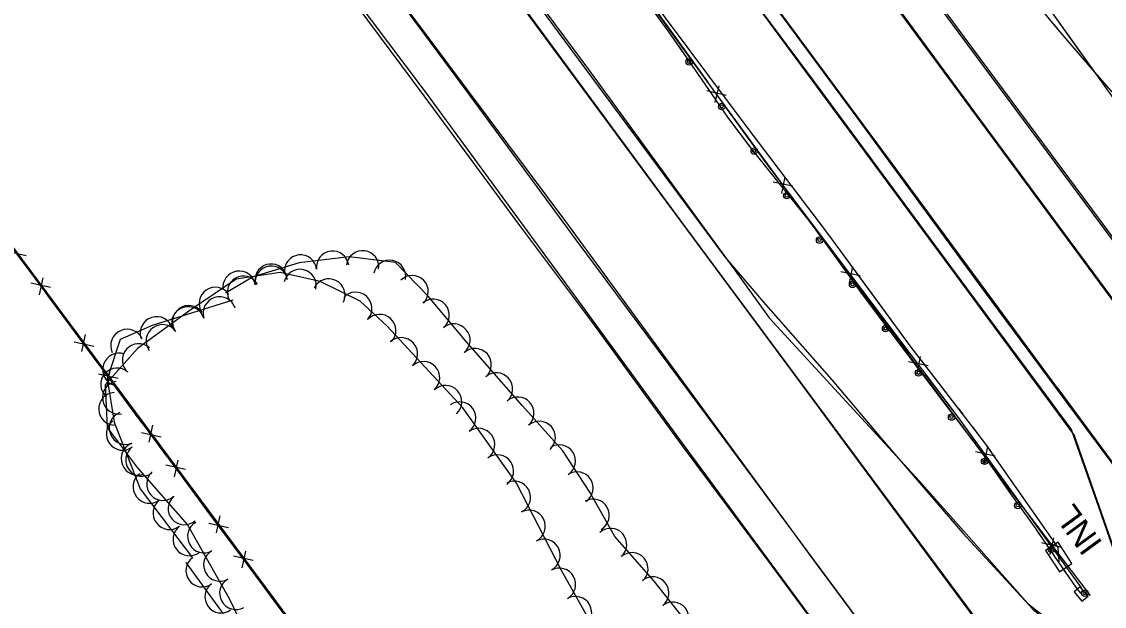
# Model space of a CAD drawing. Extents: x 353423 to 364002, y 127000 to 201942.
# Drawn here: x 360516.5 to 360782.5, y 130570.2 to 130713.8 of the extents above; entities that cross this region are included whole.
import ezdxf

# ---------------------------------------------------------------- set-up
doc = ezdxf.new("R2010")
doc.units = 0
for name, color, linetype in [('E_DTM_SlopeBottom', 7, 'Continuous'), ('E_DTM_SlopeTop', 7, 'Continuous'), ('E_FEN_Generic', 7, 'Continuous'), ('E_MISCPROP', 7, 'Continuous'), ('E_STRUCT_WingWall', 7, 'Continuous')]:
    doc.layers.add(name, color=color, linetype=linetype)

msp = doc.modelspace()

# ---------------------------------------------------------------- linework, layer by layer
at = {"layer": 'E_DTM_SlopeBottom'}
for p, q in [((360686.93, 130693.93), (360687.86, 130698.02)), ((360689.63, 130695.68), (360684.87, 130696.79)), ((360705.93, 130673.4), (360701.14, 130674.4)), ((360703.26, 130671.59), (360704.1, 130675.7)), ((360512.84, 130657.43), (360517.64, 130656.38)), ((360722.57, 130651.33), (360717.79, 130652.34)), ((360719.91, 130649.53), (360720.75, 130653.64)), ((360520.89, 130646.74), (360521.78, 130650.87)), ((360523.6, 130648.53), (360518.78, 130649.59)), ((360532.09, 130636.93), (360531.21, 130632.81)), ((360529.4, 130635.14), (360534.2, 130634.09)), ((360736.55, 130627.46), (360737.39, 130631.57)), ((360537.47, 130624.35), (360538.36, 130628.48)), ((360739.22, 130629.26), (360734.43, 130630.27)), ((360540.18, 130626.14), (360535.36, 130627.2)), ((360545.95, 130612.86), (360550.75, 130611.81)), ((360548.64, 130614.65), (360547.77, 130610.53)), ((360755.68, 130607.02), (360750.92, 130608.12)), ((360752.98, 130605.27), (360753.9, 130609.36)), ((360556.78, 130603.77), (360551.96, 130604.82)), ((360554.08, 130601.97), (360554.95, 130606.11)), ((360565.2, 130592.36), (360564.33, 130588.24)), ((360562.51, 130590.57), (360567.31, 130589.52)), ((360769.2, 130582.88), (360770.12, 130586.98)), ((360570.7, 130579.62), (360571.58, 130583.75)), ((360771.9, 130584.63), (360767.13, 130585.73)), ((360573.4, 130581.41), (360568.59, 130582.46))]:
    msp.add_line(p, q, dxfattribs=at)
for points in [[(360776.97, 130574.69), (360746.67, 130616.52), (360699.41, 130679.17), (360658.68, 130735.65), (360605.88, 130806.93), (360546.91, 130886.24), (360510.01, 130936.13), (360465.18, 130997.46), (360404.07, 131080.41), (360366.6, 131130.68)], [(361092.35, 129877.19), (361044.92, 129941.89), (360997.56, 130006.24), (360962.5, 130053.48), (360925.13, 130103.47), (360878.83, 130166.15), (360830.3, 130231.49), (360791.79, 130283.41), (360741.39, 130351.57), (360693.7, 130416.36), (360638.93, 130490.09), (360591.48, 130554.19), (360546.89, 130614.15), (360499.36, 130678.34), (360464.05, 130726.01), (360438.2, 130761.06), (360411.43, 130797.18), (360381.21, 130837.79)], [(360407.27, 130804.74), (360439.73, 130759.75), (360490.26, 130690.73), (360670.73, 130447.81), (360721.87, 130378.76), (360826.04, 130237.28), (360883.23, 130160.42), (360930.64, 130096.44), (361000.73, 130001.84), (361082.18, 129891.3), (361106.51, 129856.97), (361154.89, 129791.52), (361182.92, 129753.46), (361188.88, 129640.57), (361196.9, 129546.21), (361209.22, 129452.29), (361221.13, 129367.62), (361233.6, 129282.65)], [(360678.52, 130708.14), (360672.74, 130716.15)], [(360685.09, 130699.03), (360678.52, 130708.14)], [(360694.68, 130685.72), (360688.91, 130693.73)], [(360701.31, 130676.65), (360699.41, 130679.17), (360694.68, 130685.72)], [(360711.19, 130663.55), (360705.24, 130671.44)], [(360717.96, 130654.58), (360711.19, 130663.55)], [(360518.97, 130651.85), (360512.23, 130660.95)], [(360517.45, 130654.12), (360524.18, 130645.07)], [(360727.84, 130641.48), (360721.89, 130649.37)], [(360528.82, 130638.56), (360522.89, 130646.56)], [(360524.18, 130645.07), (360530.1, 130637.1)], [(360734.6, 130632.51), (360727.84, 130641.48)], [(360535.55, 130629.46), (360528.82, 130638.56)], [(360534.01, 130631.84), (360540.74, 130622.78)], [(360744.48, 130619.42), (360738.53, 130627.3)], [(360545.4, 130616.17), (360539.47, 130624.17)], [(360540.74, 130622.78), (360546.65, 130614.82)], [(360751.13, 130610.36), (360746.67, 130616.52), (360744.48, 130619.42)], [(360552.15, 130607.08), (360546.89, 130614.15), (360545.4, 130616.17)], [(360550.57, 130609.55), (360557.29, 130600.5)], [(360760.76, 130597.07), (360754.96, 130605.07)], [(360562.02, 130593.81), (360556.08, 130601.8)], [(360557.29, 130600.5), (360563.21, 130592.53)], [(360767.35, 130587.98), (360760.76, 130597.07)], [(360568.77, 130584.73), (360562.02, 130593.81)], [(360567.12, 130587.27), (360573.85, 130578.21)], [(360776.97, 130574.69), (360771.18, 130582.69)], [(360578.64, 130571.46), (360572.7, 130579.45)], [(360573.85, 130578.21), (360579.77, 130570.25)], [(360777.05, 130571.4), (360778.58, 130572.68), (360776.64, 130574.98), (360775.12, 130573.69), (360777.05, 130571.4)], [(360585.4, 130562.37), (360578.64, 130571.46)]]:
    msp.add_lwpolyline(points, dxfattribs=at)
msp.add_lwpolyline([(360774.59, 130580.69), (360771.16, 130585.9), (360768.1, 130583.88), (360771.53, 130578.67)], close=True, dxfattribs=at)
at = {"layer": 'E_DTM_SlopeTop'}
for points in [[(361333.55, 129917.72), (361268.46, 130006.01), (361189.85, 130112.75), (361142.67, 130176.31), (361088.86, 130249.79), (360994.04, 130376.87), (360928.62, 130465.05), (360871.56, 130543.5), (360815.21, 130618.95), (360766.71, 130684.28), (360721.66, 130745.05), (360677.21, 130805.9), (360595.4, 130915.9), (360546.5, 130984.06), (360499.99, 131045.42), (360426.96, 131144.04)], [(360419.47, 131139.59), (360478.07, 131059.84), (360541.82, 130973.68), (360588.71, 130910.37), (360647.11, 130831.47), (360699.04, 130761.76), (360750.66, 130691.62), (360805.87, 130616.86), (360864.14, 130537.84), (360910.27, 130475.6), (360951.2, 130420.07), (361004.77, 130348.23), (361046.61, 130292.04), (361097.13, 130223.94), (361149.43, 130153.39), (361185.11, 130104.98), (361238.11, 130033), (361245.88, 130022.49), (361278.08, 129978.64), (361333.1, 129905.4)], [(360337.83, 131131.57), (360358.59, 131103.63), (360410.73, 131033.01), (360469.38, 130953.56), (360514.36, 130893.15), (360555.3, 130837.54), (360604.51, 130771.17), (360655.75, 130702.06), (360692.79, 130651.26), (360700.18, 130641.04)], [(360392.82, 131129.19), (360439.78, 131065.72), (360491.21, 130996.27), (360566.57, 130894.7), (360647.89, 130784.33), (360688.43, 130729.6), (360741.87, 130657.22), (360775.19, 130612.07)], [(360770.85, 130623.99), (360731.32, 130677.71), (360684.37, 130741.2), (360627.35, 130818.29), (360564.03, 130903.58), (360518.64, 130964.96), (360463.16, 131040.47), (360396.39, 131130.9)], [(360812.38, 130484.47), (360679.44, 130663.54), (360601.08, 130770.21), (360543.32, 130848.21), (360486.67, 130924.56), (360443.57, 130982.64), (360405.94, 131033.09), (360347.68, 131112.32), (360339.61, 131123.22)], [(361334.82, 129736.64), (361276.43, 129817.07), (361218.41, 129895.06), (361173.92, 129955.59), (361116.6, 130033.88), (361057.88, 130112.91), (361005.23, 130183.79), (360919.7, 130299.92), (360859.57, 130381.04), (360802.73, 130458.17), (360712.34, 130579.92), (360650.2, 130664.74), (360583.26, 130754.37), (360522.68, 130834.6), (360443.16, 130936.49), (360381.32, 131015.53), (360355.42, 131048.77)], [(360359.06, 131031.63), (360412.77, 130962.23), (360456.51, 130906.46), (360514.58, 130829.11), (360575.61, 130749.78), (360615.66, 130696.58), (360651.09, 130648.19), (360678.79, 130610.26), (360711.14, 130566.37), (360768.38, 130488.8), (360811.24, 130431.97), (360853.39, 130374.54), (360875.99, 130343.44), (360911.98, 130295.27), (360943.46, 130251.36), (360971.6, 130213.46), (361000.8, 130174.05), (361030.19, 130135.22), (361061.21, 130091.97), (361110.81, 130026.56), (361166.93, 129950.76), (361239.61, 129851.93), (361335.43, 129723.6)], [(360915.39, 130428.25), (360885.77, 130468.28), (360854.3, 130510.8), (360823.95, 130551.75), (360794.76, 130591.46), (360773.92, 130619.47), (360751.38, 130649.91), (360722.07, 130689.97), (360692.78, 130729.59), (360658.7, 130775.33), (360626.52, 130818.94)], [(360539.14, 130812.53), (360565.51, 130777.84), (360593.87, 130739.91), (360625.54, 130697.03), (360652.65, 130660.22), (360685.53, 130616.09), (360714.56, 130576.84), (360749.27, 130530.18), (360775.57, 130494.65), (360810.61, 130447.18), (360838.14, 130409.72), (360879.43, 130354.21), (360906.49, 130317.48), (360944.28, 130266.52), (360972.83, 130227.69), (361006.65, 130182.14), (361037.04, 130141.05), (361070.51, 130095.92), (361098.26, 130058.32), (361129.55, 130016.03), (361157.08, 129978.62), (361188.2, 129936.52), (361215.22, 129899.89), (361236.43, 129871.54)], [(360787.07, 130577.55), (360781.17, 130594.57), (360775.15, 130611.63), (360774.45, 130613.59), (360767.1, 130623.57), (360748.79, 130648.37), (360729.58, 130674.29), (360711.81, 130698.39), (360689.89, 130727.84), (360668.06, 130757.8), (360647.03, 130785.8), (360625.85, 130814.41)], [(361335.19, 129902.03), (361317.97, 129925.09), (361294.2, 129957.22), (361266.66, 129994.48), (361242.03, 130027.81), (361217.11, 130061.23), (361186.78, 130102.37), (361155.57, 130144.32), (361126.8, 130183.16), (361098.06, 130221.84), (361070.02, 130259.76), (361036.43, 130304.8), (361006.19, 130345.98), (360970.52, 130394.27), (360936.12, 130440.54), (360901.22, 130487.47), (360871.26, 130528.04), (360838.83, 130571.83), (360808.58, 130612.92), (360780.05, 130651.51), (360745.78, 130697.86), (360715, 130739.66), (360684.42, 130781.1), (360659.61, 130814.18)], [(360529.26, 130810.15), (360554.27, 130777.79), (360574.26, 130750.78), (360595.98, 130721.64), (360615.36, 130695.63), (360638.79, 130663.72), (360656.49, 130640.14), (360678.56, 130609.95), (360700.65, 130580.24), (360724.42, 130548.06), (360743.96, 130521.7), (360768.43, 130488.72), (360792.03, 130456.94), (360810.78, 130431.34)], [(360570.32, 130810.78), (360600.22, 130770.91), (360638.59, 130718.65), (360671.71, 130673.89), (360707.05, 130626.12), (360742.48, 130578.27), (360774.17, 130535.49), (360800.97, 130499.08), (360825.44, 130466.23), (360849.91, 130433.42), (360876.06, 130397.89), (360904.66, 130359.17), (360936.36, 130316.65), (360963.75, 130279.7), (360997.86, 130233.57), (361031.14, 130188.46), (361063.99, 130144.35), (361101.47, 130093.76), (361133.47, 130050.11), (361168.56, 130002.53), (361203.91, 129954.89), (361239.46, 129906.99), (361266.3, 129870.87)], [(360575.18, 130810.12), (360596.24, 130781.82), (360623.79, 130744.57), (360648.33, 130711.2), (360671.72, 130679.59), (360689.22, 130656.1), (360698.8, 130644.93), (360715.58, 130625.81), (360728.01, 130611.1), (360747.76, 130588.17), (360764.98, 130569.46), (360773.42, 130562.42), (360776.51, 130560.85), (360778.18, 130560.7), (360780.45, 130560.58), (360783.15, 130561.35)], [(360974.98, 130403.77), (360946.02, 130442.35), (360923.23, 130473.25), (360897.45, 130508.23), (360870.85, 130544), (360842.47, 130582.65), (360817.74, 130615.85), (360781.38, 130665.29), (360748.12, 130710.1), (360720.12, 130748.06), (360677.4, 130806.22)], [(360700.18, 130641.03), (360737.14, 130600.93), (360763.85, 130570.82), (360769.77, 130566.08), (360773.6, 130563.21), (360776.55, 130561.69), (360780.15, 130561.12), (360782.23, 130561.45), (360784.62, 130562.66), (360787.38, 130564.54), (360788.44, 130567), (360788.91, 130570.68), (360788.59, 130574), (360775.19, 130612.07)], [(360770.85, 130623.99), (360920.54, 130421.12), (360968.13, 130357.32), (361021.12, 130285.55), (361062.98, 130229.08), (361129.94, 130138.98), (361193.82, 130052.53), (361225.46, 130009.93), (361276.5, 129940.65), (361332.79, 129864.55)]]:
    msp.add_lwpolyline(points, dxfattribs=at)
at = {"layer": 'E_FEN_Generic'}
for points in [[(360682.48, 130563), (360671.92, 130576.34), (360662.23, 130587.35), (360656.14, 130598.21), (360649.46, 130608.37), (360639.59, 130619.4), (360625.73, 130635.24), (360616.38, 130646.39), (360608.33, 130654.66), (360596.99, 130656.07), (360584.65, 130654.59), (360573.39, 130651.15), (360566.55, 130647.13)], [(360658.44, 130562.53), (360649.12, 130578.93), (360638.1, 130600.39), (360624.9, 130618.91), (360606.35, 130639), (360599.68, 130645.17), (360589.88, 130649.99), (360579.98, 130652.22), (360569.17, 130650.54), (360557.81, 130642.86), (360544.92, 130633.51), (360537.04, 130624.58), (360537.54, 130614.07), (360544.84, 130604.27), (360557.25, 130590.16), (360567.45, 130572.09), (360574.9, 130556.6)], [(360568.35, 130645.42), (360548.56, 130639.16), (360540.66, 130635.72), (360537.48, 130626.1), (360539.24, 130615.39), (360545.61, 130599.07), (360558.49, 130582.12)], [(360556.81, 130580.9), (360565.99, 130568.29)]]:
    msp.add_lwpolyline(points, dxfattribs=at)
for centre, radius, start, end in [((360585.03, 130652.55), 3.97, 6.8475, 186.8322), ((360592.91, 130653.49), 3.97, 6.8475, 186.8322), ((360600.28, 130653.57), 3.97, 352.9169, 172.9015), ((360606.91, 130651.23), 3.97, 349.039, 169.0237), ((360569.93, 130648.54), 4, 8.8639, 188.8486), ((360577.8, 130650.32), 3.97, 17.0277, 197.0124), ((360577.84, 130649.77), 4, 8.8639, 188.8486), ((360584.89, 130648.97), 4, 347.2565, 167.2412), ((360571.02, 130647.35), 3.97, 30.4164, 210.4011), ((360591.97, 130646.63), 4, 333.8499, 153.8345), ((360612.44, 130647.47), 3.97, 314.246, 134.2307), ((360564.09, 130644.57), 4, 34.0756, 214.0602), ((360598.58, 130643.34), 4, 317.2176, 137.2023), ((360565.13, 130642.17), 4.05, 17.5341, 197.5187), ((360617.62, 130641.67), 3.97, 309.9624, 129.9471), ((360557.4, 130639.73), 4.05, 17.5341, 197.5187), ((360557.55, 130640.08), 4, 35.9789, 215.9636), ((360604.45, 130637.91), 4, 317.2176, 137.2023), ((360549.67, 130637.29), 4.05, 17.5341, 197.5187), ((360551.08, 130635.39), 4, 35.9789, 215.9636), ((360622.72, 130635.59), 3.97, 309.9624, 129.9471), ((360542.43, 130634.18), 4.05, 23.5502, 203.5349), ((360545.23, 130630.68), 4, 48.5605, 228.5452), ((360609.8, 130632.18), 4, 312.7408, 132.7254), ((360540.44, 130628.31), 4.05, 71.7266, 251.7112), ((360627.94, 130629.55), 3.97, 311.1969, 131.1816), ((360539.93, 130624.69), 4, 48.5605, 228.5452), ((360615.22, 130626.31), 4, 312.7408, 132.7254), ((360633.17, 130623.58), 3.97, 311.1969, 131.1816), ((360540.4, 130621.44), 4.05, 99.3329, 279.3176), ((360620.65, 130620.43), 4, 312.7408, 132.7254), ((360539.42, 130618.68), 4, 92.6813, 272.666), ((360624.11, 130616.42), 4, 305.4716, 125.4563), ((360638.41, 130617.6), 3.97, 311.8347, 131.8193), ((360542.06, 130613.99), 4.05, 111.3452, 291.3299), ((360541.3, 130612.53), 4, 126.7181, 306.7028), ((360643.7, 130611.68), 3.97, 311.8347, 131.8193), ((360628.75, 130609.9), 4, 305.4716, 125.4563), ((360545.01, 130606.44), 4.05, 111.3452, 291.3299), ((360648.62, 130605.87), 3.97, 303.3643, 123.349), ((360546.08, 130606.12), 4, 126.7181, 306.7028), ((360633.39, 130603.39), 4, 305.4716, 125.4563), ((360547.92, 130599.54), 4.05, 127.2367, 307.2213), ((360551.21, 130600.2), 4, 131.3271, 311.3118), ((360652.98, 130599.24), 3.97, 303.3643, 123.349), ((360637.53, 130596.92), 4, 297.2086, 117.1933), ((360556.49, 130594.2), 4, 131.3271, 311.3118), ((360656.94, 130592.54), 3.97, 299.2802, 119.2649), ((360552.83, 130593.09), 4.05, 127.2367, 307.2213), ((360641.18, 130589.81), 4, 297.2086, 117.1933), ((360557.73, 130586.63), 4.05, 127.2367, 307.2213), ((360561.27, 130587.3), 4, 119.4475, 299.4322), ((360661.22, 130585.36), 3.97, 311.3484, 131.3331), ((360644.84, 130582.69), 4, 297.2086, 117.1933), ((360565.2, 130580.33), 4, 119.4475, 299.4322), ((360666.46, 130579.4), 3.97, 311.3484, 131.3331), ((360560.83, 130578.91), 3.97, 126.0407, 306.0254), ((360648.64, 130575.55), 4, 299.5858, 119.5705), ((360565.5, 130572.5), 3.97, 126.0407, 306.0254), ((360569.13, 130573.37), 4, 119.4475, 299.4322), ((360671.55, 130573.46), 3.97, 308.3867, 128.3714), ((360652.59, 130568.6), 4, 299.5858, 119.5705), ((360676.48, 130567.24), 3.97, 308.3867, 128.3714)]:
    msp.add_arc(centre, radius, start, end, dxfattribs=at)
at = {"layer": 'E_MISCPROP'}
msp.add_lwpolyline([(360779.14, 130572.84), (360757.56, 130601.16), (360709.1, 130666.11), (360653.76, 130741.93), (360609.58, 130801.27)], dxfattribs=at)
msp.add_lwpolyline([(360779.14, 130572.84), (360757.56, 130601.16), (360709.1, 130666.11), (360653.76, 130741.93), (360609.58, 130801.27)], dxfattribs=at)
for centre, radius in [((360680.52, 130703.93), 0.79), ((360680.5, 130703.96), 0.398), ((360688.52, 130692.97), 0.79), ((360688.5, 130693.01), 0.398), ((360696.52, 130682.02), 0.79), ((360696.49, 130682.05), 0.398), ((360704.51, 130671.06), 0.79), ((360704.49, 130671.1), 0.398), ((360712.57, 130660.14), 0.79), ((360712.55, 130660.18), 0.398), ((360720.68, 130649.27), 0.79), ((360720.66, 130649.31), 0.398), ((360728.79, 130638.4), 0.79), ((360728.77, 130638.43), 0.398), ((360736.9, 130627.53), 0.79), ((360736.88, 130627.56), 0.398), ((360745.01, 130616.66), 0.79), ((360744.99, 130616.69), 0.398), ((360753.12, 130605.79), 0.79), ((360753.1, 130605.82), 0.398), ((360761.3, 130594.95), 0.79), ((360761.27, 130594.99), 0.398), ((360769.52, 130584.16), 0.79), ((360769.49, 130584.2), 0.398), ((360777.74, 130573.38), 0.79), ((360777.71, 130573.41), 0.398)]:
    msp.add_circle(centre, radius, dxfattribs=at)
at = {"layer": 'E_STRUCT_WingWall'}
for points in [[(360564.35, 130994.96), (360591.08, 130958.39), (360617.07, 130919.63), (360639.79, 130889.58), (360661.49, 130860.97), (360681.66, 130834.2), (360697.6, 130810.86), (360722.75, 130777.24), (360743.2, 130749.8), (360768.63, 130717.47), (360784.71, 130695.06), (360798.65, 130676.94), (360813.5, 130656.32), (360840.51, 130620.35), (360867.84, 130585.1), (360898.21, 130544.91), (360920.78, 130515.95), (360944.48, 130484.11), (360969.8, 130448.78), (360992.09, 130420.31)], [(360539.71, 130892.11), (360556.19, 130870.52), (360573.57, 130845.95), (360596.64, 130815.78), (360620.66, 130785.88), (360637.81, 130764.68), (360655.81, 130740.6), (360674.6, 130714.75), (360695.46, 130686.95), (360714.78, 130661.45), (360734.79, 130634.17), (360753.13, 130610.35), (360771.12, 130584.61), (360771.34, 130581.21)], [(360694.8, 130812.62), (360704.86, 130799.11), (360714.3, 130787.51), (360724.1, 130775.26), (360731.75, 130764.02), (360738.62, 130754.02), (360745.84, 130744.05), (360751.98, 130735.45), (360760.8, 130724.35), (360771.11, 130711.9), (360779.58, 130702.06), (360788.3, 130692.08)], [(360759.03, 130729.67), (360768.63, 130717.47), (360776.97, 130705.85)], [(360664, 130729.33), (360674.6, 130714.75), (360680.68, 130706.64)], [(360666.8, 130723.3), (360675.45, 130711.3), (360682.61, 130701.12), (360689.93, 130690.33), (360695.97, 130682.29), (360703.18, 130673.31), (360710.39, 130664.28), (360716.91, 130655.41), (360723.14, 130646.68), (360730.08, 130637.45), (360737.15, 130628.13), (360744.83, 130617.97), (360752.56, 130607.76), (360759.52, 130597.8), (360765.46, 130589.51), (360770.29, 130582.42), (360774.58, 130576.25), (360775.77, 130574.44), (360776.76, 130573.29)], [(360674.36, 130712.82), (360675.45, 130711.3), (360675.53, 130711.19)], [(360770.2, 130713), (360771.11, 130711.9), (360771.48, 130711.47)], [(360774.09, 130708.44), (360779.58, 130702.06), (360788.3, 130692.08), (360793.39, 130686.8)], [(360677.83, 130707.92), (360682.61, 130701.12), (360689.93, 130690.33), (360694.52, 130684.21)], [(360680.68, 130706.64), (360695.46, 130686.95), (360697.6, 130684.12)], [(360779.36, 130702.51), (360780.56, 130700.85)], [(360694.52, 130684.21), (360695.97, 130682.29), (360703.18, 130673.31), (360710.39, 130664.28), (360712.47, 130661.44)], [(360699.95, 130681.03), (360701.12, 130679.48)], [(360703.46, 130676.38), (360704.64, 130674.83)], [(360706.98, 130671.74), (360708.15, 130670.19)], [(360710.5, 130667.1), (360714.78, 130661.45), (360727.24, 130644.46)], [(360714.84, 130658.22), (360716.03, 130656.61)], [(360718.37, 130653.37), (360719.53, 130651.74)], [(360721.85, 130648.48), (360723.01, 130646.85)], [(360727.24, 130644.46), (360734.79, 130634.17), (360744.18, 130621.97)], [(360725.41, 130643.65), (360730.08, 130637.45), (360737.15, 130628.13), (360742.9, 130620.52)], [(360742.9, 130620.52), (360744.83, 130617.97), (360752.56, 130607.76), (360759.52, 130597.8), (360760.01, 130597.11)], [(360746.55, 130618.9), (360747.74, 130617.36)], [(360750.11, 130614.28), (360751.29, 130612.74)], [(360753.63, 130609.64), (360754.74, 130608.05)], [(360756.96, 130604.87), (360770.52, 130585.47)], [(360762.34, 130593.86), (360763.51, 130592.23)], [(360765.83, 130588.97), (360766.95, 130587.32)], [(360769.2, 130584.01), (360770.29, 130582.42), (360770.33, 130582.36)], [(360772.61, 130579.08), (360774.58, 130576.25), (360775.77, 130574.44), (360776.76, 130573.29)]]:
    msp.add_lwpolyline(points, dxfattribs=at)

# ---------------------------------------------------------------- texts
at = {"layer": 'E_DTM_SlopeBottom'}
msp.add_text('INL', height=6, rotation=126.2091, dxfattribs=at).set_placement((360782.31, 130585.7))

doc.saveas('drawing.dxf')
